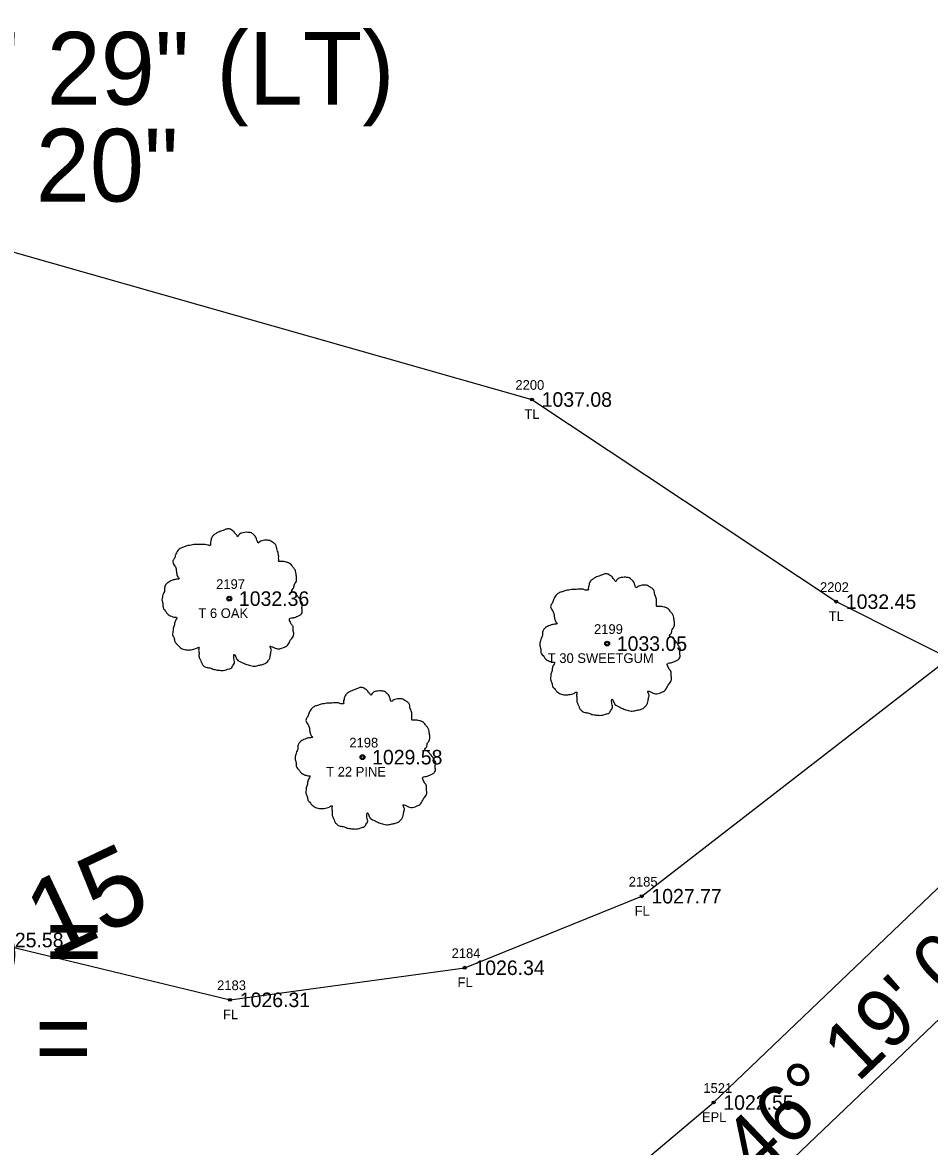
# Model space of a CAD drawing. Extents: x 1578957 to 1581675, y 1115963 to 1120391.
# Drawn here: x 1580096.1 to 1580189.7, y 1117709.5 to 1117825.5 of the extents above; entities that cross this region are included whole.
import ezdxf

# ---------------------------------------------------------------- set-up
doc = ezdxf.new("R2010")
doc.units = 0
for name, color, linetype in [('RD_EX_Fence_Other', 7, 'Continuous'), ('RD_EX_Fence_Other_txCode', 7, 'Continuous'), ('RD_EX_Road', 7, 'Continuous'), ('RD_EX_Road_txCode', 7, 'Continuous'), ('RD_EX_TX_Fence_Other_ELEV', 7, 'Continuous'), ('RD_EX_TX_Road_ELEV', 7, 'Continuous'), ('RD_EX_TX_VEG_ELEV', 7, 'Continuous'), ('RD_EX_VEG', 7, 'Continuous'), ('RD_EX_VEG_txCode', 7, 'Continuous'), ('RD_HC_Cl', 7, 'Continuous'), ('RD_HC_Data', 7, 'Continuous'), ('RD_HC_TX_Sta50', 7, 'Continuous'), ('RD_SMD_Locator', 7, 'Continuous')]:
    doc.layers.add(name, color=color, linetype=linetype)

msp = doc.modelspace()

# ---------------------------------------------------------------- linework, layer by layer
at = {"layer": 'RD_EX_Fence_Other'}
msp.add_lwpolyline([(1579823.1, 1118041.09), (1579819.64, 1117977.76), (1579811.21, 1117936.27), (1579806.91, 1117888.2), (1579805.65, 1117872.98), (1579810.22, 1117834.8), (1579821.35, 1117805.11), (1579835.23, 1117784.19), (1579851.4, 1117768.05), (1579868.55, 1117757.56), (1579908.33, 1117744.23), (1579949.73, 1117742.64), (1579998.85, 1117745.11), (1580033.64, 1117749.16), (1580057.08, 1117744.23), (1580092.08, 1117730.79), (1580117.52, 1117724.62), (1580141.72, 1117727.93), (1580159.98, 1117735.31), (1580192.44, 1117760.45), (1580226.97, 1117787.77), (1580271.31, 1117822.49), (1580302.1, 1117858.03)], dxfattribs=at)
at = {"layer": 'RD_EX_Road'}
msp.add_lwpolyline([(1580132.94, 1117689.89), (1580152.25, 1117701.26), (1580167.4, 1117714.02), (1580202.85, 1117747.92), (1580240.97, 1117781.03), (1580278.22, 1117814.01), (1580314.49, 1117848.76), (1580346.17, 1117886.72), (1580374.27, 1117928.33), (1580397.16, 1117972.42), (1580413.49, 1118019.66), (1580424.92, 1118067.62), (1580431.49, 1118116.98), (1580436.81, 1118166.42), (1580442.56, 1118216.33), (1580451.48, 1118265.26), (1580462.53, 1118314.08), (1580473.88, 1118362.54), (1580483.48, 1118411.51)], dxfattribs=at)
at = {"layer": 'RD_EX_VEG'}
msp.add_lwpolyline([(1580087.69, 1117803.9), (1580148.66, 1117786.57), (1580180.04, 1117765.71), (1580201.95, 1117754.73), (1580237.55, 1117786.67), (1580273.1, 1117820.63), (1580306.94, 1117855.17), (1580338.22, 1117894.07), (1580365.76, 1117938.41), (1580387.11, 1117979.41), (1580401.63, 1118023.89), (1580405.64, 1118038.16), (1580418.87, 1118115.49), (1580427.53, 1118167.2), (1580431.61, 1118217.5), (1580441.36, 1118268.1), (1580453.33, 1118318.55), (1580411.81, 1118312.94), (1580376.62, 1118313.13)], dxfattribs=at)
for centre, radius in [((1580117.43, 1117766.02), 0.25), ((1580117.41, 1117766), 0.0001), ((1580156.41, 1117761.38), 0.25), ((1580156.4, 1117761.37), 0.0001), ((1580131.17, 1117749.66), 0.25), ((1580131.15, 1117749.64), 0.0001)]:
    msp.add_circle(centre, radius, dxfattribs=at)
for points in [[(1580117.56, 1117773.19), (1580117.26, 1117773.21), (1580116.93, 1117773.11), (1580116.68, 1117773.01), (1580116.46, 1117772.94), (1580116.23, 1117772.84), (1580115.93, 1117772.66), (1580115.71, 1117772.46), (1580115.58, 1117772.21), (1580115.53, 1117771.99), (1580115.48, 1117771.71), (1580115.48, 1117771.54), (1580115.36, 1117771.51), (1580115.21, 1117771.54), (1580114.96, 1117771.61), (1580114.71, 1117771.61), (1580114.46, 1117771.61), (1580114.11, 1117771.59), (1580113.76, 1117771.59), (1580113.49, 1117771.54), (1580113.16, 1117771.49), (1580112.79, 1117771.36), (1580112.44, 1117771.24), (1580112.14, 1117770.99), (1580111.89, 1117770.51), (1580111.76, 1117770.16), (1580111.61, 1117769.91), (1580111.76, 1117769.46), (1580111.94, 1117769.11), (1580111.96, 1117768.91), (1580112.04, 1117768.49), (1580112.14, 1117768.26), (1580112.26, 1117768.06), (1580112.19, 1117768.04), (1580111.81, 1117767.99), (1580111.51, 1117767.89), (1580111.09, 1117767.66), (1580110.86, 1117767.44), (1580110.76, 1117767.11), (1580110.74, 1117766.76), (1580110.64, 1117766.56), (1580110.56, 1117766.29), (1580110.54, 1117766.21), (1580110.49, 1117765.89), (1580110.59, 1117765.44), (1580110.61, 1117765.09), (1580110.74, 1117764.86), (1580110.89, 1117764.69), (1580111.06, 1117764.44), (1580111.46, 1117764.21), (1580111.79, 1117764.11), (1580111.99, 1117764.09), (1580111.81, 1117763.59), (1580111.76, 1117763.24), (1580111.64, 1117762.84), (1580111.64, 1117762.76), (1580111.59, 1117762.29), (1580111.74, 1117761.96), (1580111.81, 1117761.59), (1580111.99, 1117761.37), (1580112.26, 1117761.07), (1580112.59, 1117760.84), (1580113.09, 1117760.72), (1580113.49, 1117760.74), (1580114.06, 1117760.92), (1580114.31, 1117760.99), (1580114.28, 1117760.82), (1580114.31, 1117760.44), (1580114.31, 1117760.02), (1580114.46, 1117759.69), (1580114.56, 1117759.42), (1580114.71, 1117759.17), (1580115.03, 1117758.94), (1580115.43, 1117758.87), (1580115.86, 1117758.72), (1580116.31, 1117758.64), (1580116.81, 1117758.62), (1580117.41, 1117758.77), (1580117.68, 1117758.89), (1580117.78, 1117759.07), (1580117.98, 1117759.44), (1580117.93, 1117759.67), (1580117.96, 1117760.27), (1580118.06, 1117760.09), (1580118.23, 1117759.74), (1580118.73, 1117759.44), (1580119.13, 1117759.27), (1580119.61, 1117759.12), (1580119.91, 1117759.04), (1580120.38, 1117759.12), (1580120.76, 1117759.19), (1580121.13, 1117759.32), (1580121.43, 1117759.59), (1580121.61, 1117759.87), (1580121.66, 1117760.14), (1580121.73, 1117760.52), (1580121.78, 1117760.69)], [(1580121.78, 1117760.69), (1580121.71, 1117760.87), (1580121.66, 1117761.12), (1580121.73, 1117761.09), (1580121.91, 1117761.04), (1580122.18, 1117760.92), (1580122.41, 1117760.84), (1580122.73, 1117760.87), (1580123.01, 1117760.97), (1580123.46, 1117761.24), (1580123.73, 1117761.72), (1580124.01, 1117762.11), (1580124.08, 1117762.44), (1580124.03, 1117762.66), (1580124.01, 1117763.16), (1580123.81, 1117763.41), (1580123.76, 1117763.54), (1580123.66, 1117763.94), (1580123.73, 1117763.99), (1580124.01, 1117764.04), (1580124.38, 1117764.16), (1580124.66, 1117764.29), (1580124.88, 1117764.46), (1580124.96, 1117764.69), (1580124.93, 1117765.09), (1580124.98, 1117765.49), (1580124.91, 1117765.64), (1580124.81, 1117765.79), (1580124.73, 1117765.99), (1580124.58, 1117766.14), (1580124.48, 1117766.29), (1580124.38, 1117766.39), (1580124.26, 1117766.54), (1580124.08, 1117766.66), (1580123.93, 1117766.71), (1580123.88, 1117766.86), (1580124.03, 1117767.06), (1580124.08, 1117767.16), (1580124.11, 1117767.39), (1580124.33, 1117767.74), (1580124.38, 1117768.14), (1580124.33, 1117768.56), (1580124.28, 1117768.84), (1580124.13, 1117769.11), (1580123.93, 1117769.36), (1580123.81, 1117769.54), (1580123.63, 1117769.66), (1580123.31, 1117769.79), (1580123.06, 1117769.84), (1580122.71, 1117769.84), (1580122.51, 1117769.89), (1580122.53, 1117769.94), (1580122.53, 1117770.09), (1580122.53, 1117770.36), (1580122.46, 1117770.81), (1580122.31, 1117771.31), (1580122.31, 1117771.34), (1580122.21, 1117771.59), (1580121.98, 1117771.79), (1580121.81, 1117771.89), (1580121.61, 1117772.01), (1580121.36, 1117772.04), (1580121.06, 1117772.04), (1580120.78, 1117771.99), (1580120.58, 1117771.89), (1580120.41, 1117771.76), (1580120.33, 1117771.91), (1580120.23, 1117772.21), (1580120.18, 1117772.36), (1580120.03, 1117772.54), (1580119.81, 1117772.74), (1580119.36, 1117772.86), (1580118.73, 1117772.79), (1580118.43, 1117772.59), (1580118.28, 1117772.41), (1580118.23, 1117772.54), (1580118.03, 1117772.74), (1580117.93, 1117772.91), (1580117.76, 1117773.04), (1580117.61, 1117773.14), (1580117.51, 1117773.19)], [(1580156.54, 1117768.55), (1580156.24, 1117768.58), (1580155.92, 1117768.48), (1580155.67, 1117768.38), (1580155.44, 1117768.3), (1580155.22, 1117768.2), (1580154.92, 1117768.03), (1580154.69, 1117767.83), (1580154.57, 1117767.58), (1580154.52, 1117767.35), (1580154.47, 1117767.08), (1580154.47, 1117766.9), (1580154.34, 1117766.88), (1580154.19, 1117766.9), (1580153.94, 1117766.98), (1580153.69, 1117766.98), (1580153.44, 1117766.98), (1580153.09, 1117766.95), (1580152.74, 1117766.95), (1580152.47, 1117766.9), (1580152.14, 1117766.85), (1580151.77, 1117766.73), (1580151.42, 1117766.6), (1580151.12, 1117766.35), (1580150.87, 1117765.88), (1580150.74, 1117765.53), (1580150.59, 1117765.28), (1580150.74, 1117764.83), (1580150.92, 1117764.48), (1580150.94, 1117764.28), (1580151.02, 1117763.85), (1580151.12, 1117763.63), (1580151.24, 1117763.43), (1580151.17, 1117763.4), (1580150.79, 1117763.35), (1580150.49, 1117763.25), (1580150.07, 1117763.03), (1580149.84, 1117762.8), (1580149.74, 1117762.48), (1580149.72, 1117762.13), (1580149.62, 1117761.93), (1580149.54, 1117761.66), (1580149.52, 1117761.58), (1580149.47, 1117761.26), (1580149.57, 1117760.81), (1580149.59, 1117760.46), (1580149.72, 1117760.23), (1580149.87, 1117760.06), (1580150.04, 1117759.81), (1580150.44, 1117759.58), (1580150.77, 1117759.48), (1580150.97, 1117759.46), (1580150.79, 1117758.96), (1580150.74, 1117758.61), (1580150.62, 1117758.21), (1580150.62, 1117758.13), (1580150.57, 1117757.66), (1580150.72, 1117757.33), (1580150.79, 1117756.96), (1580150.97, 1117756.73), (1580151.24, 1117756.43), (1580151.57, 1117756.21), (1580152.07, 1117756.08), (1580152.47, 1117756.11), (1580153.04, 1117756.28), (1580153.29, 1117756.36), (1580153.27, 1117756.18), (1580153.29, 1117755.81), (1580153.29, 1117755.38), (1580153.44, 1117755.06), (1580153.54, 1117754.78), (1580153.69, 1117754.53), (1580154.02, 1117754.31), (1580154.42, 1117754.23), (1580154.84, 1117754.08), (1580155.29, 1117754.01), (1580155.79, 1117753.98), (1580156.39, 1117754.13), (1580156.67, 1117754.26), (1580156.77, 1117754.43), (1580156.97, 1117754.81), (1580156.92, 1117755.03), (1580156.94, 1117755.63), (1580157.04, 1117755.46), (1580157.22, 1117755.11), (1580157.72, 1117754.81), (1580158.12, 1117754.63), (1580158.59, 1117754.48), (1580158.89, 1117754.41), (1580159.37, 1117754.48), (1580159.74, 1117754.56), (1580160.12, 1117754.68), (1580160.42, 1117754.96), (1580160.59, 1117755.23), (1580160.64, 1117755.51), (1580160.71, 1117755.88), (1580160.76, 1117756.06)], [(1580160.76, 1117756.06), (1580160.69, 1117756.23), (1580160.64, 1117756.48), (1580160.71, 1117756.46), (1580160.89, 1117756.41), (1580161.16, 1117756.28), (1580161.39, 1117756.21), (1580161.71, 1117756.23), (1580161.99, 1117756.33), (1580162.44, 1117756.61), (1580162.71, 1117757.08), (1580162.99, 1117757.48), (1580163.06, 1117757.81), (1580163.01, 1117758.03), (1580162.99, 1117758.53), (1580162.79, 1117758.78), (1580162.74, 1117758.91), (1580162.64, 1117759.31), (1580162.71, 1117759.36), (1580162.99, 1117759.41), (1580163.36, 1117759.53), (1580163.64, 1117759.66), (1580163.86, 1117759.83), (1580163.94, 1117760.06), (1580163.91, 1117760.46), (1580163.96, 1117760.86), (1580163.89, 1117761.01), (1580163.79, 1117761.16), (1580163.71, 1117761.36), (1580163.56, 1117761.51), (1580163.46, 1117761.66), (1580163.36, 1117761.76), (1580163.24, 1117761.91), (1580163.06, 1117762.03), (1580162.91, 1117762.08), (1580162.86, 1117762.23), (1580163.01, 1117762.43), (1580163.06, 1117762.53), (1580163.09, 1117762.75), (1580163.31, 1117763.1), (1580163.36, 1117763.5), (1580163.31, 1117763.93), (1580163.26, 1117764.2), (1580163.11, 1117764.48), (1580162.91, 1117764.73), (1580162.79, 1117764.9), (1580162.61, 1117765.03), (1580162.29, 1117765.15), (1580162.04, 1117765.2), (1580161.69, 1117765.2), (1580161.49, 1117765.25), (1580161.51, 1117765.3), (1580161.51, 1117765.45), (1580161.51, 1117765.73), (1580161.44, 1117766.18), (1580161.29, 1117766.68), (1580161.29, 1117766.7), (1580161.19, 1117766.95), (1580160.96, 1117767.15), (1580160.79, 1117767.25), (1580160.59, 1117767.38), (1580160.34, 1117767.4), (1580160.04, 1117767.4), (1580159.77, 1117767.35), (1580159.57, 1117767.25), (1580159.39, 1117767.13), (1580159.32, 1117767.28), (1580159.22, 1117767.58), (1580159.17, 1117767.73), (1580159.02, 1117767.9), (1580158.79, 1117768.1), (1580158.34, 1117768.23), (1580157.72, 1117768.15), (1580157.42, 1117767.95), (1580157.27, 1117767.78), (1580157.22, 1117767.9), (1580157.02, 1117768.1), (1580156.92, 1117768.28), (1580156.74, 1117768.4), (1580156.59, 1117768.5), (1580156.49, 1117768.55)], [(1580131.3, 1117756.82), (1580131, 1117756.85), (1580130.67, 1117756.75), (1580130.42, 1117756.65), (1580130.2, 1117756.57), (1580129.97, 1117756.47), (1580129.67, 1117756.3), (1580129.45, 1117756.1), (1580129.32, 1117755.85), (1580129.27, 1117755.62), (1580129.22, 1117755.35), (1580129.22, 1117755.17), (1580129.1, 1117755.15), (1580128.95, 1117755.17), (1580128.7, 1117755.25), (1580128.45, 1117755.25), (1580128.2, 1117755.25), (1580127.85, 1117755.22), (1580127.5, 1117755.22), (1580127.23, 1117755.17), (1580126.9, 1117755.12), (1580126.53, 1117755), (1580126.18, 1117754.87), (1580125.88, 1117754.62), (1580125.63, 1117754.15), (1580125.5, 1117753.8), (1580125.35, 1117753.55), (1580125.5, 1117753.1), (1580125.68, 1117752.75), (1580125.7, 1117752.55), (1580125.78, 1117752.13), (1580125.88, 1117751.9), (1580126, 1117751.7), (1580125.93, 1117751.68), (1580125.55, 1117751.63), (1580125.25, 1117751.53), (1580124.83, 1117751.3), (1580124.6, 1117751.08), (1580124.5, 1117750.75), (1580124.48, 1117750.4), (1580124.38, 1117750.2), (1580124.3, 1117749.93), (1580124.28, 1117749.85), (1580124.23, 1117749.53), (1580124.33, 1117749.08), (1580124.35, 1117748.73), (1580124.48, 1117748.5), (1580124.63, 1117748.33), (1580124.8, 1117748.08), (1580125.2, 1117747.85), (1580125.53, 1117747.75), (1580125.73, 1117747.73), (1580125.55, 1117747.23), (1580125.5, 1117746.88), (1580125.38, 1117746.48), (1580125.38, 1117746.4), (1580125.33, 1117745.93), (1580125.48, 1117745.6), (1580125.55, 1117745.23), (1580125.73, 1117745), (1580126, 1117744.7), (1580126.33, 1117744.48), (1580126.83, 1117744.35), (1580127.23, 1117744.38), (1580127.8, 1117744.55), (1580128.05, 1117744.63), (1580128.02, 1117744.45), (1580128.05, 1117744.08), (1580128.05, 1117743.65), (1580128.2, 1117743.33), (1580128.3, 1117743.05), (1580128.45, 1117742.8), (1580128.77, 1117742.58), (1580129.17, 1117742.5), (1580129.6, 1117742.35), (1580130.05, 1117742.28), (1580130.55, 1117742.25), (1580131.15, 1117742.4), (1580131.42, 1117742.53), (1580131.52, 1117742.7), (1580131.72, 1117743.08), (1580131.67, 1117743.3), (1580131.7, 1117743.9), (1580131.8, 1117743.73), (1580131.97, 1117743.38), (1580132.47, 1117743.08), (1580132.87, 1117742.9), (1580133.35, 1117742.75), (1580133.65, 1117742.68), (1580134.12, 1117742.75), (1580134.5, 1117742.83), (1580134.87, 1117742.95), (1580135.17, 1117743.23), (1580135.35, 1117743.5), (1580135.4, 1117743.78), (1580135.47, 1117744.15), (1580135.52, 1117744.33)], [(1580135.52, 1117744.33), (1580135.45, 1117744.5), (1580135.4, 1117744.75), (1580135.47, 1117744.73), (1580135.65, 1117744.68), (1580135.92, 1117744.55), (1580136.15, 1117744.48), (1580136.47, 1117744.5), (1580136.75, 1117744.6), (1580137.2, 1117744.88), (1580137.47, 1117745.35), (1580137.75, 1117745.75), (1580137.82, 1117746.08), (1580137.77, 1117746.3), (1580137.75, 1117746.8), (1580137.55, 1117747.05), (1580137.5, 1117747.18), (1580137.4, 1117747.58), (1580137.47, 1117747.63), (1580137.75, 1117747.68), (1580138.12, 1117747.8), (1580138.4, 1117747.93), (1580138.62, 1117748.1), (1580138.7, 1117748.33), (1580138.67, 1117748.73), (1580138.72, 1117749.13), (1580138.65, 1117749.28), (1580138.55, 1117749.43), (1580138.47, 1117749.63), (1580138.32, 1117749.78), (1580138.22, 1117749.93), (1580138.12, 1117750.03), (1580138, 1117750.18), (1580137.82, 1117750.3), (1580137.67, 1117750.35), (1580137.62, 1117750.5), (1580137.77, 1117750.7), (1580137.82, 1117750.8), (1580137.85, 1117751.03), (1580138.07, 1117751.38), (1580138.12, 1117751.78), (1580138.07, 1117752.2), (1580138.02, 1117752.47), (1580137.87, 1117752.75), (1580137.67, 1117753), (1580137.55, 1117753.17), (1580137.37, 1117753.3), (1580137.05, 1117753.42), (1580136.8, 1117753.47), (1580136.45, 1117753.47), (1580136.25, 1117753.52), (1580136.27, 1117753.57), (1580136.27, 1117753.72), (1580136.27, 1117754), (1580136.2, 1117754.45), (1580136.05, 1117754.95), (1580136.05, 1117754.97), (1580135.95, 1117755.22), (1580135.72, 1117755.42), (1580135.55, 1117755.52), (1580135.35, 1117755.65), (1580135.1, 1117755.67), (1580134.8, 1117755.67), (1580134.52, 1117755.62), (1580134.32, 1117755.52), (1580134.15, 1117755.4), (1580134.07, 1117755.55), (1580133.97, 1117755.85), (1580133.92, 1117756), (1580133.77, 1117756.17), (1580133.55, 1117756.37), (1580133.1, 1117756.5), (1580132.47, 1117756.42), (1580132.17, 1117756.22), (1580132.02, 1117756.05), (1580131.97, 1117756.17), (1580131.77, 1117756.37), (1580131.67, 1117756.55), (1580131.5, 1117756.67), (1580131.35, 1117756.77), (1580131.25, 1117756.82)]]:
    msp.add_spline(points, degree=3, dxfattribs=at)
at = {"layer": 'RD_HC_Cl'}
msp.add_line((1580164.51, 1117697.67), (1580209.09, 1117740.25), dxfattribs=at)
msp.add_arc((1579994.83, 1117500.9), 216.03, 59.7409, 93.2323, dxfattribs=at)
at = {"layer": 'RD_SMD_Locator'}
for centre in [(1580148.66, 1117786.57), (1580117.43, 1117766.02), (1580180.04, 1117765.71), (1580156.41, 1117761.38), (1580131.17, 1117749.66), (1580159.98, 1117735.31), (1580141.72, 1117727.93), (1580117.52, 1117724.62), (1580167.4, 1117714.02)]:
    msp.add_circle(centre, 0.15, dxfattribs=at)

# ---------------------------------------------------------------- texts
at = {"layer": 'RD_EX_Fence_Other_txCode'}
for s, p in [('2185', (1580158.64, 1117736.31)), ('FL', (1580159.25, 1117733.31)), ('2184', (1580140.37, 1117728.93)), ('2183', (1580116.18, 1117725.62)), ('FL', (1580140.98, 1117725.93)), ('FL', (1580116.79, 1117722.62))]:
    msp.add_text(s, height=1, dxfattribs=at).set_placement(p)
at = {"layer": 'RD_EX_Road_txCode'}
for s, p in [('1521', (1580166.34, 1117715.02)), ('EPL', (1580166.19, 1117712.02))]:
    msp.add_text(s, height=1, dxfattribs=at).set_placement(p)
at = {"layer": 'RD_EX_TX_Fence_Other_ELEV'}
for s, p in [('1027.77', (1580160.98, 1117734.56)), ('1025.58', (1580093.08, 1117730.04)), ('1026.34', (1580142.72, 1117727.18)), ('1026.31', (1580118.52, 1117723.87))]:
    msp.add_text(s, height=1.5, dxfattribs=at).set_placement(p)
at = {"layer": 'RD_EX_TX_Road_ELEV'}
msp.add_text('1022.55', height=1.5, dxfattribs=at).set_placement((1580168.4, 1117713.27))
at = {"layer": 'RD_EX_TX_VEG_ELEV'}
for s, p in [('1037.08', (1580149.66, 1117785.82)), ('1032.36', (1580118.43, 1117765.27)), ('1032.45', (1580181.04, 1117764.96)), ('1033.05', (1580157.41, 1117760.63)), ('1029.58', (1580132.17, 1117748.91))]:
    msp.add_text(s, height=1.5, dxfattribs=at).set_placement(p)
at = {"layer": 'RD_EX_VEG_txCode'}
for s, p in [('2200', (1580146.95, 1117787.57)), ('TL', (1580147.88, 1117784.57)), ('2197', (1580116.08, 1117767.02)), ('2202', (1580178.37, 1117766.71)), ('T 6 OAK', (1580114.25, 1117764.02)), ('TL', (1580179.27, 1117763.71)), ('2199', (1580155.06, 1117762.38)), ('T 30 SWEETGUM', (1580150.29, 1117759.38)), ('2198', (1580129.82, 1117750.66)), ('T 22 PINE', (1580127.43, 1117747.66))]:
    msp.add_text(s, height=1, dxfattribs=at).set_placement(p)
at = {"layer": 'RD_HC_Data'}
for s, p in [('    = 33%%d 29\' 29" (LT)', (1580045, 1117817)), ('D = 26%%d 31\' 20"', (1580045, 1117807)), ('P.C. - LG% = ', (1580045, 1117727)), ('P.T. - LG% = ', (1580045, 1117717))]:
    msp.add_text(s, height=7.5, dxfattribs=at).set_placement(p)
msp.add_text('N 46%%d 19\' 04" E', height=6, rotation=43.6822, dxfattribs=at).set_placement((1580166.07, 1117700.54))
at = {"layer": 'RD_HC_TX_Sta50'}
msp.add_text('15', height=8, rotation=25.3178, dxfattribs=at).set_placement((1580099, 1117728.72))

doc.saveas('drawing.dxf')
